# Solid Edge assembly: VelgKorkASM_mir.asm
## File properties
Author: KULL
Template: Iso Metric Assembly.asm
Last saved by: KULL
Revision: 2
Application: Solid Edge
Username: KULL
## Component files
Velg2_mir.par
VeljekorkASM_mir.asm
Rehv1_mir.par
VelgKorkASM.asm
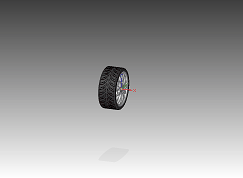
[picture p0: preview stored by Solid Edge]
